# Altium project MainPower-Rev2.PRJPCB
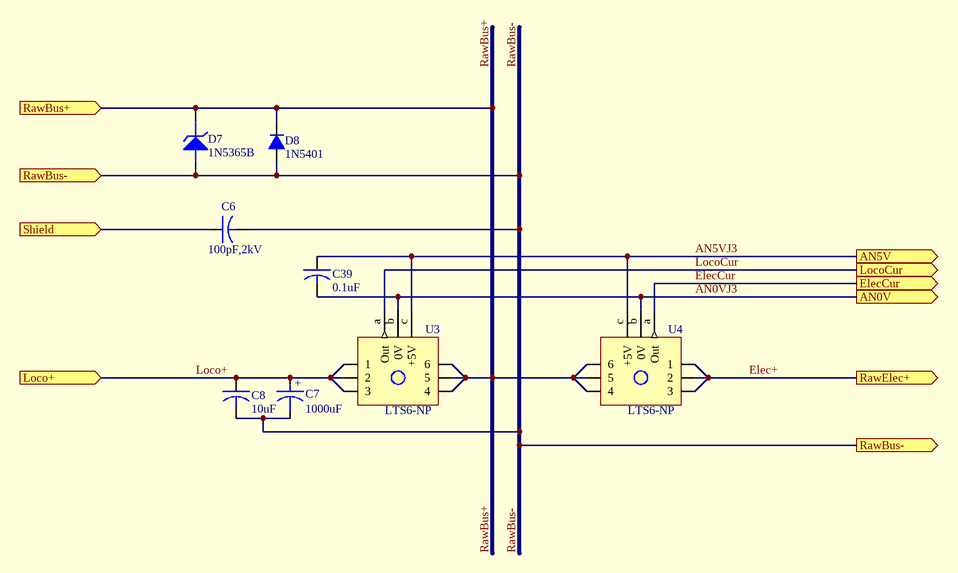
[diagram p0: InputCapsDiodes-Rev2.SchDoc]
8 sheets, 90 parts. Net scope: flat (ports and power ports of the same name join across sheets).
Board file: MainPower-Rev2.PcbDoc
Sheets:
  InputCapsDiodes-Rev2.SchDoc
  Iso5V-25W-MVC-Rev2.SchDoc
  Iso12V-30W-MVC-Rev2.SchDoc
  Iso9V-1W-Parosci-Rev2.SchDoc
  NonIso3.3V-5W-GPS-Rev2.SchDoc
  NonIso5V-13W-Iridium-Rev2.SchDoc
  BattBacked-Rev2.SCHDOC
  Watchdog-Rev2.SchDoc

## Sheet InputCapsDiodes-Rev2.SchDoc
size Tabloid; Organization: Monterey Bay Aquarium Research Institute; Address1: 7700 Sandholdt Rd; Address2: Moss Landing, CA 95039-9644; CompanyName: MBARI

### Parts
C6  100pF,2kV  [ECK]
C7  1000uF  [RAD0.3L_0.63D]
C8  10uF  [CAPSTICK-CS4-5]
C39  0.1uF  [1206]
D7  1N5365B  [DO-201AD]
D8  1N5401  [DO-201AD]
U3  LTS6-NP  [LTS6-NP]
U4  LTS6-NP  [LTS6-NP]

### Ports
AN0V (out), AN5V (out), ElecCur (out), Loco+ (in), LocoCur (out), RawBus+ (in), RawBus- (in), RawBus- (out), RawElec+ (out), Shield (in)

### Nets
AN0VJ3: C39.2 U3.b(0V) U4.b(0V) ; port AN0V
AN5VJ3: C39.1 U3.c(+5V) U4.c(+5V) ; port AN5V
Elec+: U4.1 U4.2 U4.3 ; port RawElec+
ElecCur: U4.a(Out) ; port ElecCur
Loco+: C7.1 C8.1 U3.1 U3.2 U3.3 ; port Loco+
LocoCur: U3.a(Out) ; port LocoCur
RawBus+: D7.2(K) D8.2(A) U3.4 U3.5 U3.6 U4.4 U4.5 U4.6 ; port RawBus+
RawBus-: C6.2 C7.2 C8.2 D7.1(A) D8.1(K) ; port RawBus-
Shield: C6.1 ; port Shield

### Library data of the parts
C6 = CAPACITOR: ManufPartNo: ECK-T3D101KB; Manufacturer: Panasonic; VendorPartNo: PCC2092CT-ND; Cost/ea: 0.99; Reference: T033, 764; Vendor: Digi-Key
C7 = CAPACITOR POL: Capacitor; ManufPartNo: EEU-FC1H102; Manufacturer: Panasonic; VendorPartNo: P10333-ND; Cost/ea: 1.485; Vendor: Digi-Key
C8 = CAPACITOR: ManufPartNo: 106K050CS4G; Manufacturer: ITW Paktron; VendorPartNo: AMP50V106-K10G; Cost/ea: 8.04; Vendor: Future
C39 = CAPACITOR: ManufPartNo: C1206C104J5RACTU; Manufacturer: Kemet; VendorPartNo: 399-1250-1-ND; Cost/ea: 0.253; Reference: T033, 785; Vendor: Digi-Key
D7 = ZENER3: Zener Diode; ManufPartNo: 2EZ36D5; Manufacturer: Microsemi; VendorPartNo: 2EZ36D5MSCT-ND; Cost/ea: 0.75; Vendor: Digi-Key
D8 = DIODE_S: Diode; ManufPartNo: 1N5401-T; Manufacturer: Diodes Inc; VendorPartNo: 1N5401DICT-ND; Cost/ea: 0.41; Reference: T033, 578; Vendor: Digi-Key
U3 U4 = LTS6-NP: Current Transducer; Manufacturer: LEM; VendorPartNo: 398-1000-ND; Vendor: Digi-Key; Cost/ea: 19.20

## Sheet Iso5V-25W-MVC-Rev2.SchDoc
size Tabloid; Organization: Monterey Bay Aquarium Research Institute; Address1: 7700 Sandholdt Rd; Address2: Moss Landing, CA 95039-9644; CompanyName: MBARI
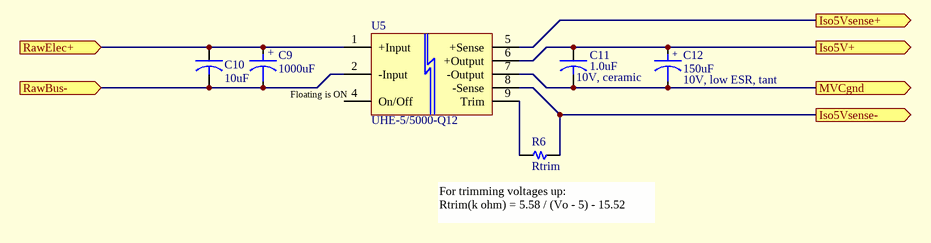
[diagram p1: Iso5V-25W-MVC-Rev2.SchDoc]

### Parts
C9  1000uF  [RAD0.3L_0.63D]
C10  10uF  [CAPSTICK-CS4-5]
C11  1.0uF  DescSheet: 10V, ceramic  [1206]
C12  150uF  DescSheet: 10V, low ESR, tant  [7343pol]
R6  Rtrim  [AXIAL0.7]
U5  UHE-5/5000-Q12  [DATEL-UHE]

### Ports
Iso5V+ (out), Iso5Vsense+ (out), Iso5Vsense- (out), MVCgnd (out), RawBus- (in), RawElec+ (in)

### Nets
MVCgnd: C11.2 C12.2 U5.7(-Output) ; port MVCgnd
Elec+: C9.1 C10.1 U5.1(+Input) ; port RawElec+
Iso5V+: C11.1 C12.1 U5.6(+Output) ; port Iso5V+
Iso5Vsense+: U5.5(+Sense) ; port Iso5Vsense+
Iso5Vsense-: R6.2 U5.8(-Sense) ; port Iso5Vsense-
RawBus-: C9.2 C10.2 U5.2(-Input) ; port RawBus-
NetR6_1: R6.1 U5.9(Trim)

Not connected (* = marked no-connect by the designer): U5 4(On/Off)

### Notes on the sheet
- (near U5) Floating is ON
- (near R6) For trimming voltages up:
  Rtrim(k ohm) = 5.58 / (Vo - 5) - 15.52

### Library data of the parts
C9 = CAPACITOR POL: Capacitor; ManufPartNo: EEU-FC1H102; Manufacturer: Panasonic; VendorPartNo: P10333-ND; Cost/ea: 1.485; Reference: T033, 696; Vendor: Digi-Key
C10 = CAPACITOR: as C8 on sheet InputCapsDiodes-Rev2
C11 = CAPACITOR: ManufPartNo: C1206C105K4RACTU; Manufacturer: Kemet; VendorPartNo: 399-1254-1-ND; Cost/ea: 0.33; Reference: T033, 785; Vendor: Digi-Key
C12 = CAPACITOR POL: Tantalum Capacitor; ManufPartNo: EEJ-L1AD157R; Manufacturer: Panasonic; VendorPartNo: P11289CT-ND; Cost/ea: 1.884; Reference: T033, 718; Vendor: Digi-Key
R6 = RESISTOR
U5 = UHE: Datel UHE DC->DC Isolated Converter; Cost/ea: 61.90

## Sheet Iso12V-30W-MVC-Rev2.SchDoc
size Tabloid; Organization: Monterey Bay Aquarium Research Institute; Address1: 7700 Sandholdt Rd; Address2: Moss Landing, CA 95039-9644; CompanyName: MBARI
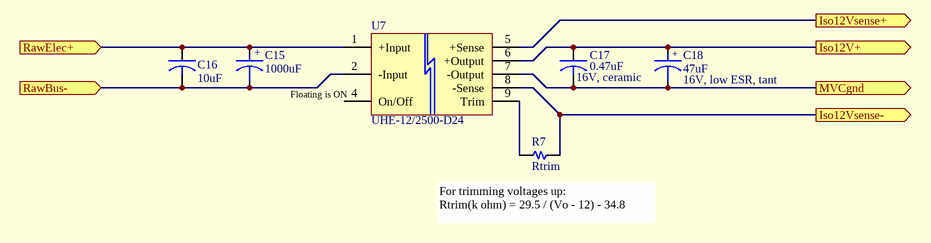
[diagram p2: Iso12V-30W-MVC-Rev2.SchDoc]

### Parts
C15  1000uF  [RAD0.3L_0.63D]
C16  10uF  [CAPSTICK-CS4-5]
C17  0.47uF  DescSheet: 16V, ceramic  [1206]
C18  47uF  DescSheet: 16V, low ESR, tant  [7343pol]
R7  Rtrim  [AXIAL0.7]
U7  UHE-12/2500-D24  [DATEL-UHE]

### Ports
Iso12V+ (out), Iso12Vsense+ (out), Iso12Vsense- (out), MVCgnd (out), RawBus- (in), RawElec+ (in)

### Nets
MVCgnd: C17.2 C18.2 U7.7(-Output) ; port MVCgnd
Elec+: C15.1 C16.1 U7.1(+Input) ; port RawElec+
Iso12V+: C17.1 C18.1 U7.6(+Output) ; port Iso12V+
Iso12Vsense+: U7.5(+Sense) ; port Iso12Vsense+
Iso12Vsense-: R7.2 U7.8(-Sense) ; port Iso12Vsense-
RawBus-: C15.2 C16.2 U7.2(-Input) ; port RawBus-
NetR7_1: R7.1 U7.9(Trim)

Not connected (* = marked no-connect by the designer): U7 4(On/Off)

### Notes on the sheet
- (near U7) Floating is ON
- (near R7) For trimming voltages up:
  Rtrim(k ohm) = 29.5 / (Vo - 12) - 34.8

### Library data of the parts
C15 = CAPACITOR POL: as C9 on sheet Iso5V-25W-MVC-Rev2
C16 = CAPACITOR: as C8 on sheet InputCapsDiodes-Rev2
C17 = CAPACITOR: ManufPartNo: ECJ-3VB1C474K; Manufacturer: Panasonic; VendorPartNo: PCC1878CT-ND; Cost/ea: 0.255; Reference: T033, 773; Vendor: Digi-Key
C18 = CAPACITOR POL: Tantalum Capacitor; ManufPartNo: EEJ-L1CD476R; Manufacturer: Panasonic; VendorPartNo: P11291CT-ND; Cost/ea: 1.605; Reference: T033, 718; Vendor: Digi-Key
R7 = RESISTOR
U7 = UHE: Datel UHE DC->DC Isolated Converter; Cost/ea: 58.90

## Sheet Iso9V-1W-Parosci-Rev2.SchDoc
size Tabloid; Organization: Monterey Bay Aquarium Research Institute; Address1: 7700 Sandholdt Rd; Address2: Moss Landing, CA 95039-9644; CompanyName: MBARI
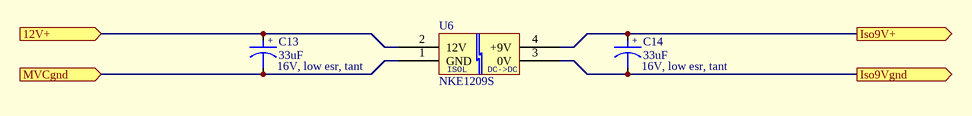
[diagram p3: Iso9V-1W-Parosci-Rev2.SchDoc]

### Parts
C13  33uF  DescSheet: 16V, low esr, tant  [6032pol]
C14  33uF  DescSheet: 16V, low esr, tant  [6032pol]
U6  NKE1209S  [NKEDCDC]

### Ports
12V+ (in), Iso9V+ (out), Iso9Vgnd (out), MVCgnd (in)

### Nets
MVCgnd: C13.2 U6.1(GND) ; port MVCgnd
12V+: C13.1 U6.2(12V) ; port 12V+
Iso9V+: C14.1 U6.4(+9V) ; port Iso9V+
Iso9Vgnd: C14.2 U6.3(0V) ; port Iso9Vgnd

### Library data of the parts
C13 C14 = CAPACITOR POL: Capacitor; ManufPartNo: EEJ-L1CC336R; Manufacturer: Panasonic; VendorPartNo: P11290CT-ND; Cost/ea: 1.057; Reference: T033, 718; Vendor: Digi-Key
U6 = NKE1209S: DC->DC Isol Converter 12->9VDC; Manufacturer: C&D Technologies; VendorPartNo: 580-NKE1209S; Cost/ea: 8.33; Reference: Cat616, 1032; Vendor: Mouser

## Sheet NonIso3.3V-5W-GPS-Rev2.SchDoc
size Tabloid; Organization: Monterey Bay Aquarium Research Institute; Address1: 7700 Sandholdt Rd; Address2: Moss Landing, CA 95039-9644; CompanyName: MBARI
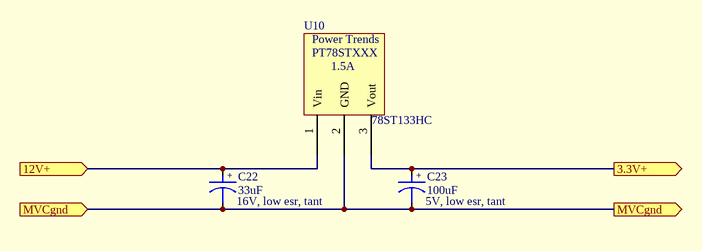
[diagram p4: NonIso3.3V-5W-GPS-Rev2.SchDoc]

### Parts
C22  33uF  DescSheet: 16V, low esr, tant  [6032pol]
C23  100uF  DescSheet: 5V, low esr, tant  [6032pol]
U10  78ST133HC  [PT78ST-HORIZ]

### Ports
3.3V+ (out), 12V+ (in), MVCgnd (in), MVCgnd (out)

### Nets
MVCgnd: C22.2 C23.2 U10.2(GND) ; port MVCgnd
3.3V+: C23.1 U10.3(Vout) ; port 3.3V+
12V+: C22.1 U10.1(Vin) ; port 12V+

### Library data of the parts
C22 = CAPACITOR POL: as C13 on sheet Iso9V-1W-Parosci-Rev2
C23 = CAPACITOR POL: Capacitor; ManufPartNo: EEJ-L0JC107R; Manufacturer: Panasonic; VendorPartNo: P11284CT-ND; Cost/ea: 1.196; Reference: T033, 718; Vendor: Digi-Key
U10 = PT78STXXX: Power Trends Switching Reg; Manufacturer: TI Power Trends; VendorPartNo: 78ST133HC-ND; Cost/ea: 15.38; Reference: T033, 1102; Vendor: Digi-Key

## Sheet NonIso5V-13W-Iridium-Rev2.SchDoc
size Tabloid; Organization: Monterey Bay Aquarium Research Institute; Address1: 7700 Sandholdt Rd; Address2: Moss Landing, CA 95039-9644; CompanyName: MBARI
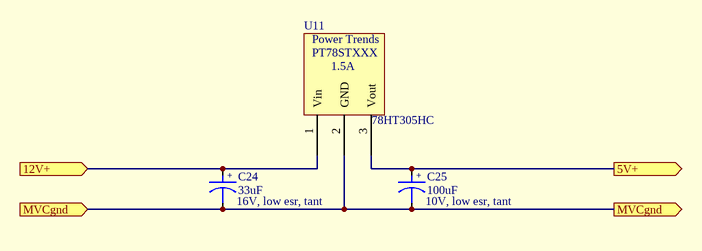
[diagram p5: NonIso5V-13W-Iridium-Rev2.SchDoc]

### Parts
C24  33uF  DescSheet: 16V, low esr, tant  [6032pol]
C25  100uF  DescSheet: 10V, low esr, tant  [7343pol]
U11  78HT305HC  [PT78ST-HORIZ]

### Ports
5V+ (out), 12V+ (in), MVCgnd (in), MVCgnd (out)

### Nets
MVCgnd: C24.2 C25.2 U11.2(GND) ; port MVCgnd
5V+: C25.1 U11.3(Vout) ; port 5V+
12V+: C24.1 U11.1(Vin) ; port 12V+

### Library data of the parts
C24 = CAPACITOR POL: as C13 on sheet Iso9V-1W-Parosci-Rev2
C25 = CAPACITOR POL: Capacitor; ManufPartNo: EEJ-L1AD107R; Manufacturer: Panasonic; VendorPartNo: P11288CT-ND; Cost/ea: 1.688; Reference: T033, 718; Vendor: Digi-Key
U11 = PT78STXXX: Power Trends Switching Reg 5V, 3A; Manufacturer: TI Power Trends; VendorPartNo: 78HT305HC-ND; Cost/ea: 22.50; Reference: T033, 1103; Vendor: Digi-Key

## Sheet BattBacked-Rev2.SCHDOC
size Tabloid; Organization: Monterey Bay Aquarium Research Institute; Address1: 7700 Sandholdt Rd; Address2: Moss Landing, CA 95039-9644; CompanyName: MBARI
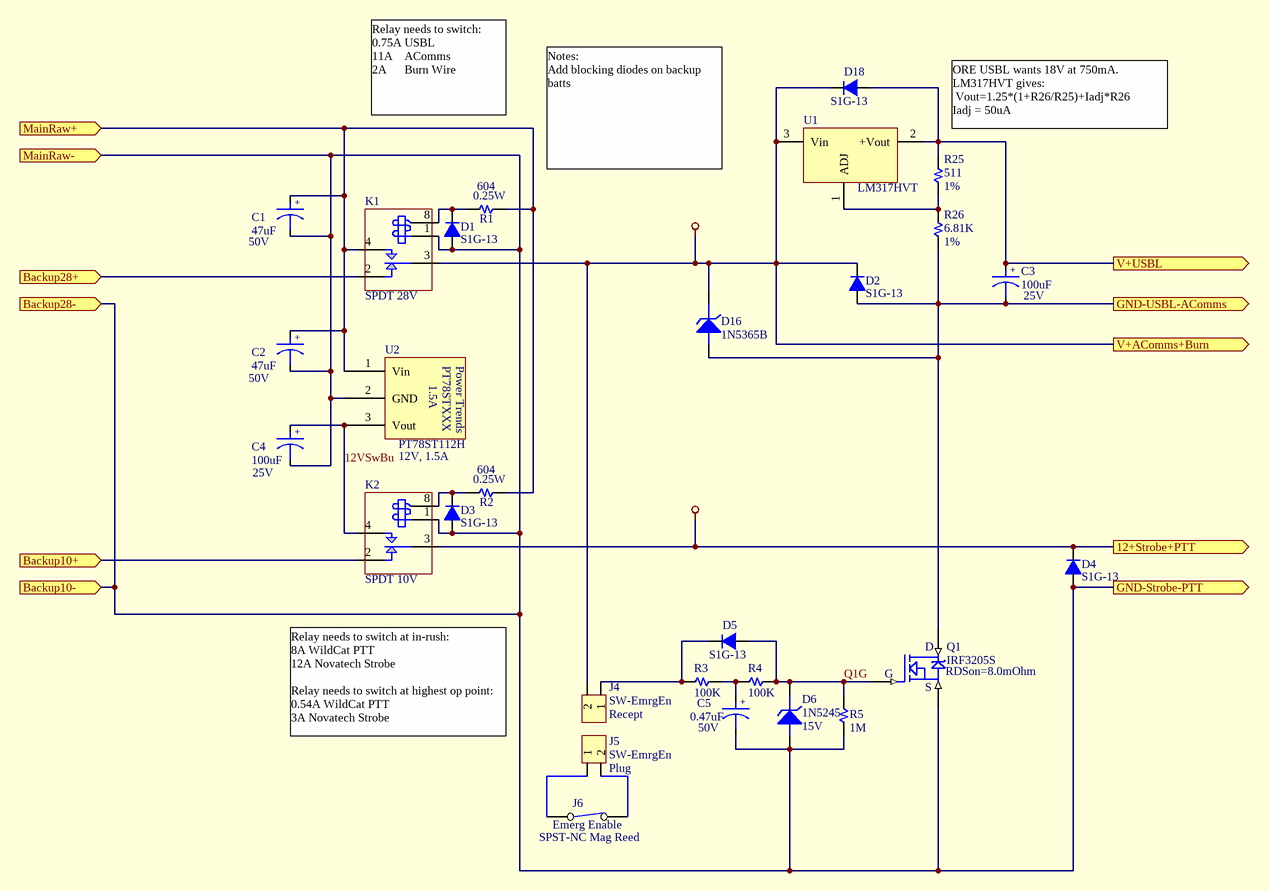
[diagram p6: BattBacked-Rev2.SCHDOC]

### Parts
C1  47uF  DescSheet: 50V  [RAD0.1L_0.25D]
C2  47uF  DescSheet: 50V  [RAD0.1L_0.25D]
C3  100uF  DescSheet: 25V  [RAD0.1L_0.25D]
C4  100uF  DescSheet: 25V  [RAD0.1L_0.25D]
C5  0.47uF  DescSheet: 50V  [RAD0.2_POL]
D1  S1G-13  [SMA]
D2  S1G-13  [SMA]
D3  S1G-13  [SMA]
D4  S1G-13  [SMA]
D5  S1G-13  [SMA]
D6  1N5245  DescSheet: 15V  [DIODE0.4]
D16  1N5365B  [DO-201AD]
D18  S1G-13  [SMA]
J4  SW-EmrgEn  DescSheet: Recept  [CGRID2]
J5  SW-EmrgEn  DescSheet: Plug  [CGRID2]  (mechanical)
J6  Emerg Enable  DescSheet: SPST-NC Mag Reed  [CGRID2]  (mechanical)
K1  SPDT 28V  [NAIS-LZ]
K2  SPDT 10V  [NAIS-LZ]
Q1  IRF3205S  DescSheet: RDSon=8.0mOhm  [D2PAK]
R1  604  DescSheet: 0.25W  [AXIAL0.7]
R2  604  DescSheet: 0.25W  [AXIAL0.7]
R3  100K  [1206]
R4  100K  [1206]
R5  1M  [1206]
R25  511  DescSheet: 1%  [1206]
R26  6.81K  DescSheet: 1%  [1206]
U1  LM317HVT  [TO-220]
U2  PT78ST112H  DescSheet: 12V, 1.5A  [PT78ST-HORIZ]

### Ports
12+Strobe+PTT (out), Backup10+ (in), Backup10- (in), Backup28+ (in), Backup28- (in), GND-Strobe-PTT (out), GND-USBL-AComms (out), MainRaw+ (in), MainRaw- (in), V+AComms+Burn (out), V+USBL (out)

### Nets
SW10VDC: D4.2(A) K2.3(COMMON) ; port 12+Strobe+PTT
SW28VDC: D2.2(A) D16.2(K) D18.2(A) J4.2 K1.3(COMMON) U1.3(Vin) ; port V+AComms+Burn
12VSwBu: C4.1 K2.4(NO) U2.3(Vout)
Backup10+: K2.2(NC) ; port Backup10+
Backup10-: C1.2 C2.2 C4.2 C5.2 D1.1(K) D3.1(K) D4.1(K) D6.1(A) K1.1(COIL+) K2.1(COIL+) Q1.3(S) R5.1 U2.2(GND) ; port Backup28-, port MainRaw-, port Backup10-, port GND-Strobe-PTT
Backup28+: K1.2(NC) ; port Backup28+
GND-USBL-AComms: C3.2 D2.1(K) D16.1(A) Q1.2(D) R26.1 ; port GND-USBL-AComms
MainRaw+: C1.1 C2.1 K1.4(NO) R1.2 R2.2 U2.1(Vin) ; port MainRaw+
Q1G: D5.1(K) D6.2(K) Q1.1(G) R4.2 R5.2
V+USBL: C3.1 D18.1(K) R25.1 U1.2(+Vout) ; port V+USBL
NetC5_1: C5.1 R3.2 R4.1
NetD1_2: D1.2(A) K1.8(COIL-) R1.1
NetD3_2: D3.2(A) K2.8(COIL-) R2.1
NetD5_2: D5.2(A) J4.1 R3.1
NetR25_2: R25.2 R26.2 U1.1(ADJ)

Not connected (* = marked no-connect by the designer): J5 1 2; J6 1(COMMON) 2(NO); K1 5(NO) 6(COMMON) 7(NC); K2 5(NO) 6(COMMON) 7(NC)

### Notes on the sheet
- Relay needs to switch:
  0.75A USBL
  11A    AComms
  2A      Burn Wire
- ORE USBL wants 18V at 750mA.
  LM317HVT gives:
  Vout=1.25*(1+R26/R25)+Iadj*R26
  Iadj = 50uA
- Notes:
  Add blocking diodes on backup batts
- Relay needs to switch at in-rush:
  8A WildCat PTT
  12A Novatech Strobe
  Relay needs to switch at highest op point:
  0.54A WildCat PTT
  3A Novatech Strobe

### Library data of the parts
C1 C2 = CAPACITOR POL: Capacitor; ManufPartNo: EEU-FC1H470; Manufacturer: Panasonic; VendorPartNo: P10321-ND; Cost/ea: 0.23; Reference: T033, 695; Vendor: Digi-Key
C3 C4 = CAPACITOR POL: Capacitor; ManufPartNo: EEU-FC1E101S; Manufacturer: Panasonic; VendorPartNo: P10269-ND; Cost/ea: 0.23; Reference: T033, 694; Vendor: Digi-Key
C5 = CAPACITOR POL: Capacitor; ManufPartNo: 222237012474; Manufacturer: BC Components; VendorPartNo: 3017PH-ND; Cost/ea: 0.348; Reference: T033, 736; Vendor: Digi-Key
D1-D5 D18 = DIODE_S: Diode; Manufacturer: Diodes Inc; VendorPartNo: S1GDICT-ND; Cost/ea: 0.288; DescSheet: 1A, 400V; Reference: T033, 578; Vendor: Digi-Key
D6 = ZENER3: Zener Diode; ManufPartNo: 1N5245B; Manufacturer: Diodes Inc; VendorPartNo: 1N5245BDICT-ND; Cost/ea: 0.21; Reference: T033, 564; Vendor: Digi-Key
D16 = ZENER3: Zener Diode; ManufPartNo: 2EZ36D5; Manufacturer: Microsemi; VendorPartNo: 2EZ36D5MSCT-ND; Cost/ea: 0.75; Reference: T033, 555; Vendor: Digi-Key
J4 = CON2: Connector; ManufPartNo: 70543-0001; Manufacturer: Molex; VendorPartNo: WM4800-ND; Cost/ea: 0.711; Reference: T033, 94; Vendor: Digi-Key
J5 = CON2: Connector; Manufacturer: Molex; VendorPartNo: WM2900-ND; Cost/ea: 0.38; Reference: T033, 94; Vendor: Digi-Key
J6 = SW-SPST-NC: Manufacturer: Molex; VendorPartNo: WM2900-ND; Cost/ea: 0.38; Reference: T033, 94; Vendor: Digi-Key
K1 K2 = RELAY-NAIS-LZ-SPDT: Nais LZ Relay SPDT; ManufPartNo: ALZ12F24; VendorPartNo: 255-1447-ND; Cost/ea: 2.16; Reference: T033, 942; Vendor: Digi-Key
Q1 = HEXFET-N: HexFET; Manufacturer: International Rectifier; VendorPartNo: IRF3205S-ND; Cost/ea: 2.72; Reference: T033, 549; Vendor: Digi-Key
R1 R2 = RESISTOR: ManufPartNo: MFR-25FBF-604R; Manufacturer: Yaego; VendorPartNo: 604XBK-ND; Cost/ea: 0.108; Reference: T033, 807; Vendor: Digi-Key
R3 R4 = RESISTOR: ManufPartNo: ERJ-8ENF1003V; Manufacturer: Panasonic; VendorPartNo: P100KFCT-ND; Cost/ea: 0.117; Reference: T033, 801; Vendor: Digi-Key
R5 = RESISTOR: ManufPartNo: ERJ-8ENF1004V; Manufacturer: Panasonic; VendorPartNo: P1.00MFCT-ND; Cost/ea: 0.117; Reference: T033, 801; Vendor: Digi-Key
R25 = RESISTOR: ManufPartNo: ERJ-8ENF5110V; Manufacturer: Panasonic; VendorPartNo: P511FCT-ND; Cost/ea: 0.117; Reference: T033, 801; Vendor: Digi-Key
R26 = RESISTOR: ManufPartNo: ERJ-8ENF6811V; Manufacturer: Panasonic; VendorPartNo: P6.81KFCT-ND; Cost/ea: 0.117; Reference: T033, 801; Vendor: Digi-Key
U1 = LM317HVT: Regulator; Manufacturer: National Semi; VendorPartNo: LM317HVT-ND; Cost/ea: 2.79; Reference: T033, 446; Vendor: Digi-Key
U2 = PT78STXXX: Power Trends Switching Reg; Manufacturer: TI PowerTrends; VendorPartNo: PT78ST112H-ND; Cost/ea: 14.46; Reference: T033, 1104; Vendor: Digi-Key

## Sheet Watchdog-Rev2.SchDoc
size Tabloid; Organization: Monterey Bay Aquarium Research Institute; Address1: 7700 Sandholdt Rd; Address2: Moss Landing, CA 95039-9644; CompanyName: MBARI
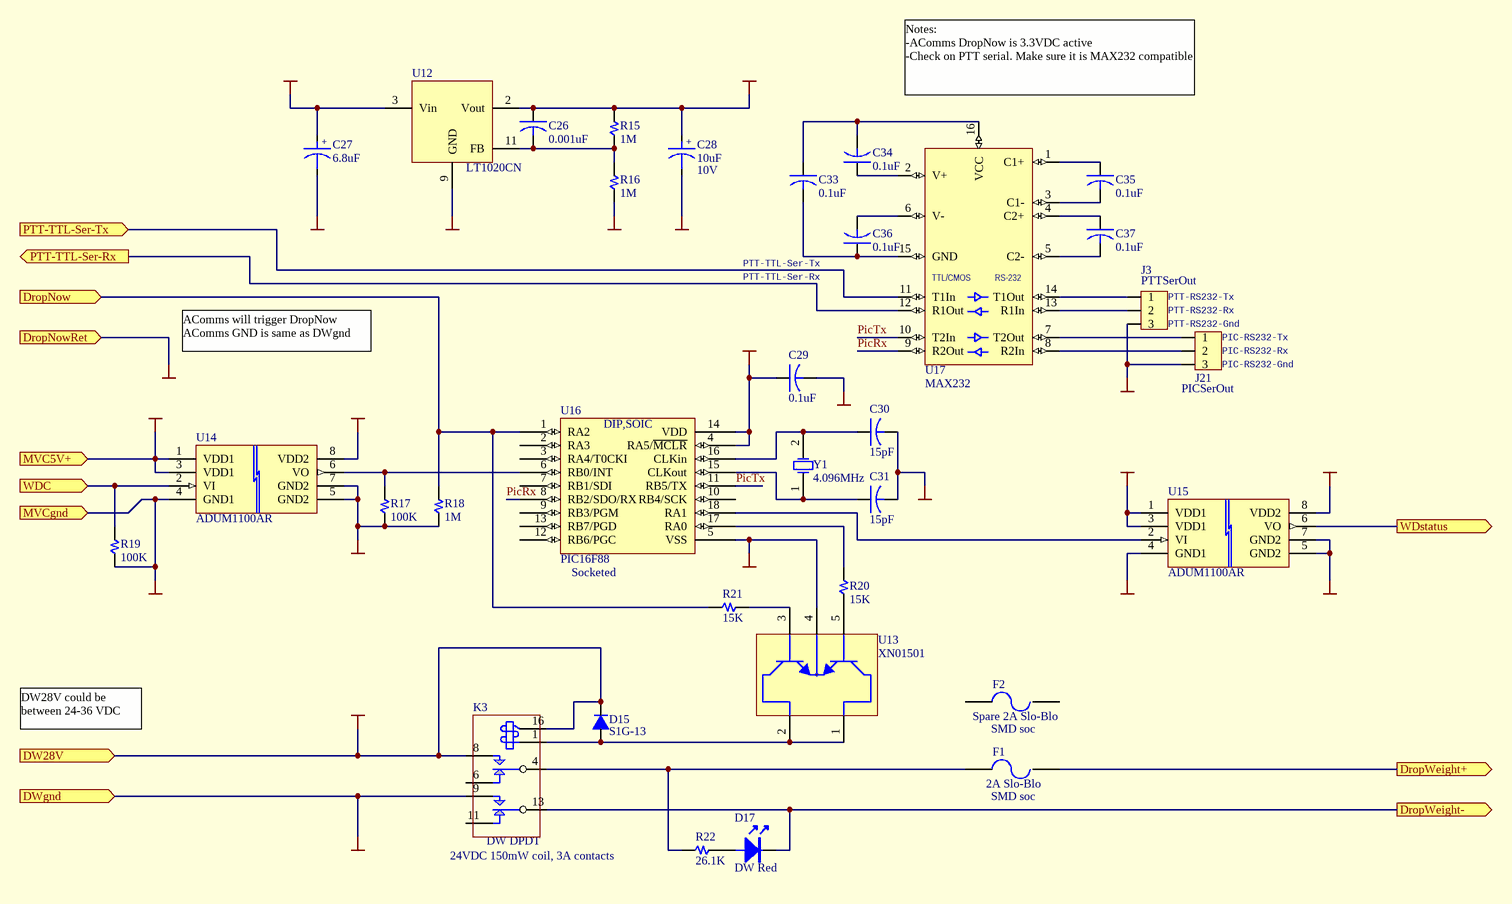
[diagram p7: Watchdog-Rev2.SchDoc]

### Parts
C26  0.001uF  [1206]
C27  6.8uF  [7343pol]
C28  10uF  DescSheet: 10V  [6032pol]
C29  0.1uF  [1206]
C30  15pF  [1206]
C31  15pF  [1206]
C33  0.1uF  [1206]
C34  0.1uF  [1206]
C35  0.1uF  [1206]
C36  0.1uF  [1206]
C37  0.1uF  [1206]
D15  S1G-13  [SMA]
D17  DW Red  [SOT-23]
F1  2A Slo-Blo  DescSheet: SMD soc  [SMF-OMNIBLOK]
F2  Spare 2A Slo-Blo  DescSheet: SMD soc  [SMF-OMNIBLOK]
J3  PTTSerOut  [CGRID3]
J21  PICSerOut  [CGRID3]
K3  DW DPDT  DescSheet: 24VDC 150mW coil, 3A contacts  [DIP16]
R15  1M  [1206]
R16  1M  [1206]
R17  100K  [1206]
R18  1M  [1206]
R19  100K  [1206]
R20  15K  [1206]
R21  15K  [1206]
R22  26.1K  [1206]
U12  LT1020CN  [DIP14]
U13  XN01501  [SC-74A]
U14  ADUM1100AR  [SO-G8/D5]
U15  ADUM1100AR  [SO-G8/D5]
U16  PIC16F88  DescSheet: Socketed  [DIP18]
U17  MAX232  [SOIC-16-0.15W]
Y1  4.096MHz  [MA-506]

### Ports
DropNow (in), DropNowRet (in), DropWeight+ (out), DropWeight- (out), DW28V (in), DWgnd (in), MVC5V+ (in), MVCgnd (in), PTT-TTL-Ser-Rx (out), PTT-TTL-Ser-Tx (in), WDC (in), WDstatus (out)

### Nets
DW5V: C26.1 C28.1 C29.1 R15.1 U12.2(Vout) U14.8(VDD2) U15.1(VDD1) U15.3(VDD1) U16.4(RA5/~{MCLR}) U16.14(VDD)
DW28V: C27.1 D15.2(A) K3.8(NO1) K3.16(COIL) U12.3(Vin) ; port DW28V
DWgnd: C27.2 C28.2 C29.2 C30.2 C31.2 J3.3 J21.3 K3.9(NO2) R16.2 R17.2 R18.2 U12.9(GND) U13.4(Emitter) U14.5(GND2) U14.7(GND2) U15.4(GND1) U16.5(VSS) ; port DWgnd, port DropNowRet
MVC5V+: U14.1(VDD1) U14.3(VDD1) U15.8(VDD2) ; port MVC5V+
MVCgnd: R19.2 U14.4(GND1) U15.5(GND2) U15.7(GND2) ; port MVCgnd
DropNow: R18.1 R21.2 U16.1(RA2) ; port DropNow
DropWeight+: F1.2 ; port DropWeight+
DropWeight-: D17.3(K) K3.13(COMMON2) ; port DropWeight-
PicRx: U16.8(RB2/SDO/RX) U17.9(R2Out)
PicTx: U16.11(RB5/TX) U17.10(T2In)
PTT-TTL-Ser-Rx: U17.12(R1Out) ; port PTT-TTL-Ser-Rx
PTT-TTL-Ser-Tx: U17.11(T1In) ; port PTT-TTL-Ser-Tx
WDC: R19.1 U14.2(VI) ; port WDC
WDstatus: U15.6(VO) ; port WDstatus
NetC26_2: C26.2 R15.2 R16.1 U12.11(FB)
NetC30_1: C30.1 U16.16(CLKin) Y1.2(OSC2)
NetC31_1: C31.1 U16.15(CLKout) Y1.1(OSC1)
NetC33_1: C33.1 C34.2 U17.16(VCC)
NetC33_2: C33.2 C36.1 U17.15(GND)
NetC34_1: C34.1 U17.2(V+)
NetC35_1: C35.1 U17.1(C1+)
NetC35_2: C35.2 U17.3(C1-)
NetC36_2: C36.2 U17.6(V-)
NetC37_1: C37.1 U17.4(C2+)
NetC37_2: C37.2 U17.5(C2-)
NetD15_1: D15.1(K) K3.1(COIL) U13.1(C1) U13.2(C2)
NetD17_2: D17.2(A) R22.1
NetF1_1: F1.1 K3.4(COMMON1) R22.2
NetJ3_1: J3.1 U17.14(T1Out)
NetJ3_2: J3.2 U17.13(R1In)
NetJ21_1: J21.1 U17.7(T2Out)
NetJ21_2: J21.2 U17.8(R2In)
NetR17_1: R17.1 U14.6(VO) U16.6(RB0/INT)
NetR20_1: R20.1 U13.5(B1)
NetR20_2: R20.2 U16.17(RA0)
NetR21_1: R21.1 U13.3(B2)
NetU15_2: U15.2(VI) U16.18(RA1)

Not connected (* = marked no-connect by the designer): F2 1 2; K3 6(NC1) 11(NC2); U16 2(RA3) 3(RA4/T0CKI) 7(RB1/SDI) 9(RB3/PGM) 10(RB4/SCK) 12(RB6/PGC) 13(RB7/PGD)

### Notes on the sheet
- Notes:
  -AComms DropNow is 3.3VDC active
  -Check on PTT serial. Make sure it is MAX232 compatible
- PTT-TTL-Ser-Tx
- PTT-TTL-Ser-Rx
- AComms will trigger DropNow
  AComms GND is same as DWgnd
- PTT-RS232-Tx
- PTT-RS232-Rx
- (near J21) PTT-RS232-Gnd
- (near J21) PIC-RS232-Tx
- (near J21) PIC-RS232-Gnd
- (near J21) PIC-RS232-Rx
- DW28V could be between 24-36 VDC

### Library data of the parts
C26 = CAPACITOR: ManufPartNo: C1206C102K5RACTU; Manufacturer: Kemet; VendorPartNo: 399-1221-1-ND; Cost/ea: 0.132; DescSheet: 10V; Reference: T033, 785; Vendor: Digi-Key
C27 = CAPACITOR POL: Capacitor; ManufPartNo: T491D685M050AS; Manufacturer: Panasonic; VendorPartNo: 399-3109-1-ND; Cost/ea: 0.79; DescSheet: 50V; Reference: T033, 727; Vendor: Digi-Key
C28 = CAPACITOR POL: Capacitor; ManufPartNo: T491C106K010AS; Manufacturer: Panasonic; VendorPartNo: 399-1571-1-ND; Cost/ea: 0.32; Reference: T033, 726; Vendor: Digi-Key
C29 C33-C37 = CAPACITOR: as C39 on sheet InputCapsDiodes-Rev2
C30 C31 = CAPACITOR: ManufPartNo: C1206C150J5GACTU; Manufacturer: Kemet; VendorPartNo: 399-1194-1-ND; Cost/ea: 0.171; Reference: T033, 784; Vendor: Digi-Key
D15 = DIODE_S: as D1 on sheet BattBacked-Rev2
D17 = LED: ManufPartNo: SML-LX15SRC-TR; Manufacturer: Lumex; VendorPartNo: 67-1660-1-ND; Cost/ea: 0.494; Reference: T033, 1194; Vendor: Digi-Key
F1 F2 = Fuse 2: Fuse; Manufacturer: Littelfuse; ManufPartNo: 0154002.DRT; VendorPartNo: F1305CT-ND; Cost/ea: 2.63; Reference: T033, 1066; Vendor: Digi-Key
J3 J21 = CON3: Connector; ManufPartNo: 70543-0002; Manufacturer: Molex; VendorPartNo: WM4801-ND; Cost/ea: 0.89; Reference: T033, 94; Vendor: Digi-Key
K3 = RELAY-PB-V23105: P&B V23105 Relay DPDT; ManufPartNo: V23105A5005A201; VendorPartNo: PB385-ND; Cost/ea: 1.78; Reference: T033, 946; Vendor: Digi-Key
R15 R16 R18 = RESISTOR: as R5 on sheet BattBacked-Rev2
R17 R19 = RESISTOR: as R3 on sheet BattBacked-Rev2
R20 R21 = RESISTOR: ManufPartNo: ERJ-8ENF1502V; Manufacturer: Panasonic; VendorPartNo: P15.0KFCT-ND; Cost/ea: 0.117; Reference: T033, 801; Vendor: Digi-Key
R22 = RESISTOR: ManufPartNo: ERJ-8ENF2612V; Manufacturer: Panasonic; VendorPartNo: P26.1KFCT-ND; Cost/ea: 0.117; DescSheet: 1/10W; Reference: T033, 801; Vendor: Digi-Key
U12 = LT1020: Micropower Regulator; Manufacturer: Linear Technology; VendorPartNo: LT1020CN-ND; Cost/ea: 6.88; Reference: T033, 463; Vendor: Digi-Key
U13 = XN01501: Dual NPN Common Emitter Transistor; ManufPartNo: XN0150100L; Manufacturer: Panasonic; VendorPartNo: XN0150100LCT-ND; Cost/ea: 0.41; Reference: T033, 529; Vendor: Digi-Key
U14 U15 = ADUM1100AR: Digital Isolator; Manufacturer: Analog Devices; Cost/ea: 4.19; Vendor: Arrow Electronics
U16 = PIC16F88: PIC16F88 microcontroller DIP,SOIC package; ManufPartNo: PIC16F88-I/P; Manufacturer: Microchip; VendorPartNo: PIC16F88-I/P-ND; Cost/ea: 4.58; Reference: T033, 303; Vendor: Digi-Key
U17 = MAX232: MAX232 Communications Chip; ManufPartNo: MAX232ACSE; Manufacturer: Maxim; VendorPartNo: MAX232ACSE-ND; Cost/ea: 5.51; Reference: T033, 483; Vendor: Digi-Key
Y1 = XTAL: Crystal Oscillator; pin to pad: 2>4; Manufacturer: Epson Elec; ManufPartNo: MA-506 4.0960M-C0; VendorPartNo: SE2619CT-ND; Cost/ea: 2.80; Reference: T033, 611; Vendor: Digi-Key

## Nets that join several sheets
MVCgnd: Iso5V-25W-MVC-Rev2 (C11.2 C12.2 U5.7), Iso12V-30W-MVC-Rev2 (C17.2 C18.2 U7.7), Iso9V-1W-Parosci-Rev2 (C13.2 U6.1), NonIso3.3V-5W-GPS-Rev2 (C22.2 C23.2 U10.2), NonIso5V-13W-Iridium-Rev2 (C24.2 C25.2 U11.2), Watchdog-Rev2 (R19.2 U14.4 U15.5 U15.7)
12V+: Iso9V-1W-Parosci-Rev2 (C13.1 U6.2), NonIso3.3V-5W-GPS-Rev2 (C22.1 U10.1), NonIso5V-13W-Iridium-Rev2 (C24.1 U11.1)
Elec+: InputCapsDiodes-Rev2 (U4.1 U4.2 U4.3), Iso5V-25W-MVC-Rev2 (C9.1 C10.1 U5.1), Iso12V-30W-MVC-Rev2 (C15.1 C16.1 U7.1)
RawBus-: InputCapsDiodes-Rev2 (5 pins), Iso5V-25W-MVC-Rev2 (C9.2 C10.2 U5.2), Iso12V-30W-MVC-Rev2 (C15.2 C16.2 U7.2)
